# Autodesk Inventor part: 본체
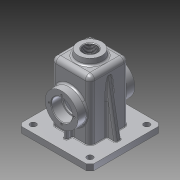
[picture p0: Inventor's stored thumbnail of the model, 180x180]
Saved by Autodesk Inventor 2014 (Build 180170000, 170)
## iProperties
Created: 2017-08
Part Number: 본체
Material: 알루미늄 6061
Document SubType Name: Modeling
Designer: user
Density: 2.71 g/cm^3
Appearance: 알루미늄 - 평지
Mass: 798.825 g
Surface Area: 901.718 cm^2
Volume: 294.769 cm^3
Author: user
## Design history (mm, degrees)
sketch "스케치1"
  geometry: L1 (32.5, -32.5)-(-32.5, -32.5); L2 (-32.5, -32.5)-(-32.5, 32.5); L3 (-32.5, 32.5)-(32.5, 32.5); L4 (32.5, 32.5)-(32.5, -32.5); L5 (32.5, -32.5)-(-32.5, 32.5); L6 (-32.5, -32.5)-(32.5, 32.5); 1 further point
  constraints: 12 end point, 2 midpoint, 2 parallel, 2 perpendicular, 1 horizontal
  dimensions: "d0" = 65 distance of L2.end L3.end
extrude "돌출1" new body sketch "스케치1" distance "d1" = 110; taper "d2" = 0 deg
fillet "모깎기1" dims "d3" = 8
fillet "모깎기2" dims "d4" = 8
feature "쉘1" dims "d5" = 5
node "작업 평면1"
sketch "스케치3"
  geometry: L1 (24.5, 0)-(-24.5, 0) reference; C1 r 27.5 at (0, 55); 2 further points
  constraints: 1 centre point, 1 midpoint, 1 vertical alignment
  dimensions: "d9" = 55 distance of point (0, 0) C1.centre; "d10" = 55 diameter of C1
extrude "돌출2" join sketch "스케치3" stored distance "d11" = 10; taper "d12" = 0 deg
hole "구멍1" diameter "d15" = 30; stored, may be unused: countersink angle "d19" = 90 deg, drill point angle "d21" = 0 deg; dims "d13" = 10, "d14" = 10, "d16" = 6, "d17" = 35, "d18" = 17, "d20" = 8
sketch "스케치4"
  geometry: C1 r 17.5 at (0, 0) reference; 2 further points
  constraints: 1 vertical alignment
  dimensions: "d22" = 21 distance of point (0, 21) C1.centre
hole "구멍2" sketch "스케치4" at (0, 21) diameter "d23" = 3.242; stored, may be unused: countersink angle "d27" = 90 deg, drill point angle "d29" = 118 deg; dims "d24" = 8, "d25" = 35, "d26" = 17, "d28" = 10
node "작업 평면2"
sketch "스케치5"
  geometry: C1 r 20 at (0, 0); 1 further point
  constraints: 1 centre point, 1 coincident
  dimensions: "d34" = 40 diameter of C1
extrude "돌출3" join sketch "스케치5" stored distance "d35" = 10; taper "d36" = 7 deg
hole "구멍3" diameter "d39" = 22.835; stored, may be unused: countersink angle "d43" = 90 deg, drill point angle "d45" = 0 deg; dims "d37" = 10, "d38" = 10, "d40" = 8, "d41" = 35, "d42" = 17, "d44" = 10
sketch "스케치6"
  geometry: L1 (24.5, 32.5)-(-24.5, 32.5) reference; L2 (-32.5, 24.5)-(-32.5, -24.5) reference; L3 (-24.5, -32.5)-(24.5, -32.5) reference; L4 (32.5, -24.5)-(32.5, 24.5) reference; L5 (60, -60)-(-60, -60); L6 (-60, -60)-(-60, 60); L7 (-60, 60)-(60, 60); L8 (60, 60)-(60, -60); L9 (60, -60)-(-60, 60); L10 (-60, -60)-(60, 60); L11 (-60, 54.343)-(-54.343, 60); L12 (-60, -54.343)-(-54.343, -60); L13 (54.343, -60)-(60, -54.343); L14 (54.343, 60)-(60, 54.343); A1 r 8 centre (-24.5, 24.5) between (-24.5, 32.5) and (-32.5, 24.5) reference; A2 r 8 centre (-24.5, -24.5) between (-32.5, -24.5) and (-24.5, -32.5) reference; A3 r 8 centre (24.5, -24.5) between (24.5, -32.5) and (32.5, -24.5) reference; A4 r 8 centre (24.5, 24.5) between (32.5, 24.5) and (24.5, 32.5) reference; 1 further point
  constraints: 20 end point, 8 perpendicular, 8 point on line, 3 parallel, 2 midpoint, 1 horizontal
  dimensions: "d46" = 120 distance of L6.end L7.end; "d47" = 8 distance of L11.start L11.end
extrude "돌출4" join sketch "스케치6" distance "d48" = 10; taper "d49" = 0 deg
sketch "스케치7"
  geometry: L1 (-32.5, 10)-(-32.5, 102) reference; L2 (54.343, 10)-(-54.343, 10) reference; L3 (-48, 10)-(-32.5, 97.905); L4 (-60, 0)-(-60, 10) reference; 1 further point
  constraints: 2 end point, 2 point on line
  dimensions: "d50" = 10 deg angle of L3 L4; "d51" = 12 distance of L4.end L3.start
feature "리브1" sketch "스케치7" dims "d52" = 1, "d53" = 10, "d54" = 0, "d55" = 0, "d56" = 1, "d57" = 1
sketch "스케치8"
  geometry: L1 (-47.5, 27.5)-(-32.5, 27.5) reference; L2 (54.343, 10)-(-54.343, 10) reference; L3 (-27.5, 0)-(-27.5, 102) reference; L4 (-42.5, 27.5)-(-42.5, 10); 1 further point
  constraints: 2 end point, 2 point on line, 1 perpendicular
  dimensions: "d58" = 15 distance between parallel lines of L3 L4
feature "리브2" sketch "스케치8" dims "d59" = 1, "d60" = 6, "d61" = 0, "d62" = 0, "d63" = 1, "d64" = 1
sketch "스케치9"
  geometry: L1 (54.343, 60)-(-54.343, 60) reference; 3 further points
  constraints: 1 vertical alignment
  dimensions: "d65" = 47.5 horizontal distance of point (-47.5, 47.5) point (0, 0); "d66" = 95 distance of point (-47.5, -47.5) point (-47.5, 47.5); "d67" = 12.5 distance from line of L1 point (-47.5, 47.5)
hole "구멍4" sketch "스케치9" at (-47.5, 47.5), (-47.5, -47.5) diameter "d68" = 10; stored, may be unused: countersink angle "d72" = 90 deg, drill point angle "d74" = 0 deg; dims "d69" = 8, "d70" = 35, "d71" = 17, "d73" = 10
chamfer "모따기1" distance "d75" = 1; stored, may be unused: second distance "d76" = 2, angle "d77" = 45 deg
chamfer "모따기2" distance "d78" = 1; stored, may be unused: second distance "d79" = 2, angle "d80" = 45 deg
chamfer "모따기3" distance "d81" = 1; stored, may be unused: second distance "d82" = 2, angle "d83" = 45 deg
fillet "모깎기3" dims "d84" = 3
fillet "모깎기4" dims "d85" = 3
fillet "모깎기5" dims "d86" = 3
fillet "모깎기6" dims "d87" = 3
fillet "모깎기7" dims "d88" = 3
fillet "모깎기8" dims "d89" = 3
fillet "모깎기9" dims "d90" = 3
fillet "모깎기10" dims "d91" = 1
sketch "스케치10"
  geometry: L1 (44.5, -18)-(4.5, -18) reference; L2 (57, 0)-(57, 91) reference; 2 further points
  constraints: 1 other
  dimensions: "d92" = 26 distance from line of L1 point (24.5, 8); "d93" = 32.5 distance from line of L2 point (24.5, 8)
feature "엠보싱1" sketch "스케치10" dims "d94" = 0.5, "d95" = 0
node "솔리드1"
pattern_circular "원형 패턴1" dims angle "d31" = 360 deg
mirror "대칭1"
mirror "대칭2"
mirror "대칭3"
mirror "대칭4"
node "작업 평면3"
other parameters: "d8" = -47.5
